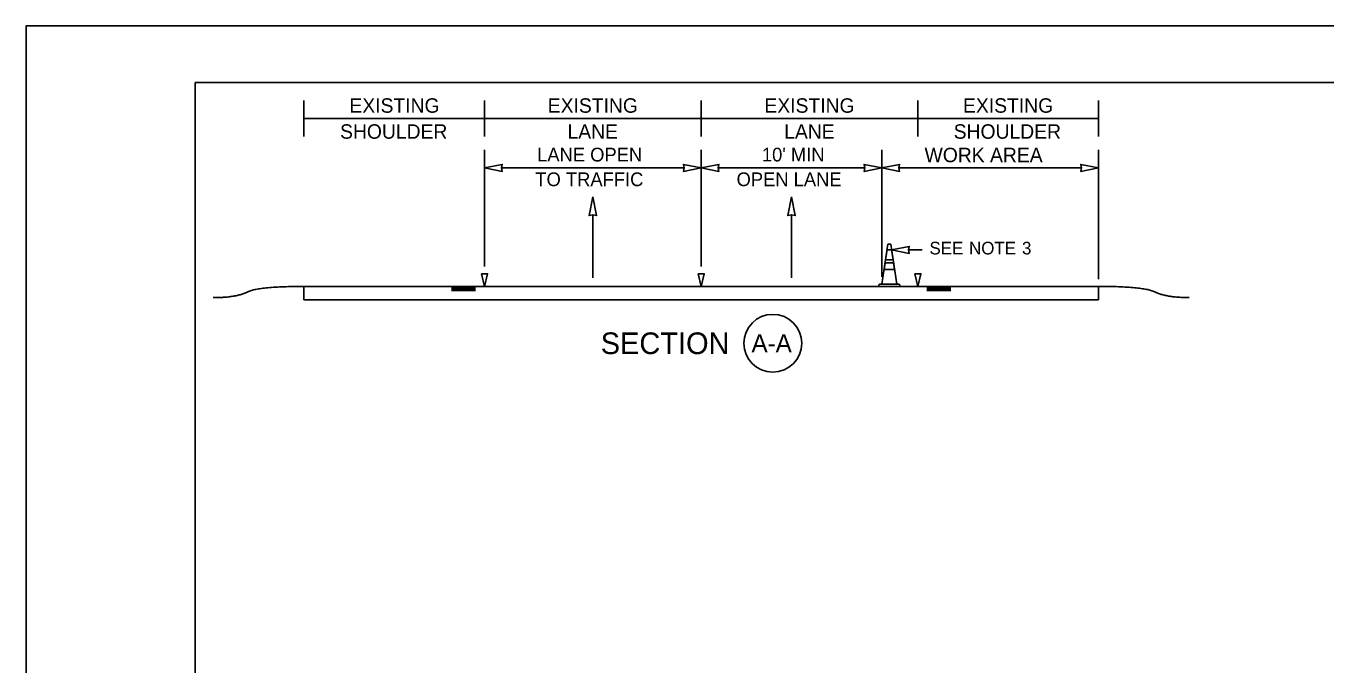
# Model space of a CAD drawing. Extents: x 99999.1 to 100055.7, y 99995 to 100010.7.
# Drawn here: x 100019.06 to 100026.26, y 100007.15 to 100010.69 of the extents above; entities that cross this region are included whole.
import ezdxf

# ---------------------------------------------------------------- set-up
doc = ezdxf.new("R2010")
doc.units = 0
for name, color, linetype in [('SH_GI_PlotLimits', 7, 'Continuous'), ('SH_GI_SheetBorder', 7, 'Continuous'), ('SH_TI_WZSectionCut', 7, 'Continuous'), ('TR_WZ_ArrowLeftStrRightTurn', 7, 'Continuous'), ('TR_WZ_TrafficConeElev', 7, 'Continuous'), ('TR_WZ_WorkZoneDetails', 7, 'Continuous'), ('TR_WZ_WorkZoneTextCurrent', 7, 'Continuous')]:
    doc.layers.add(name, color=color, linetype=linetype)

msp = doc.modelspace()

# ---------------------------------------------------------------- linework, layer by layer
at = {"layer": 'SH_GI_PlotLimits'}
msp.add_lwpolyline([(100019.0625, 99999.6875), (100036.0625, 99999.6875), (100036.0625, 100010.6875), (100019.0625, 100010.6875)], close=True, dxfattribs=at)
at = {"layer": 'SH_GI_SheetBorder'}
for q in [(100020, 100000), (100035.75, 100010.375)]:
    msp.add_line((100020, 100010.375), q, dxfattribs=at)
at = {"layer": 'SH_TI_WZSectionCut'}
for p, q in [((100020.6021, 100010.075), (100020.6021, 100010.275)), ((100021.6021, 100010.075), (100021.6021, 100010.275)), ((100022.8021, 100010.075), (100022.8021, 100010.275)), ((100024.0021, 100010.075), (100024.0021, 100010.275)), ((100025.0021, 100010.075), (100025.0021, 100010.275)), ((100020.6021, 100010.175), (100021.6021, 100010.175)), ((100021.6021, 100010.175), (100022.8021, 100010.175)), ((100022.8021, 100010.175), (100024.0021, 100010.175)), ((100024.0021, 100010.175), (100025.0021, 100010.175)), ((100021.6021, 100009.3547), (100021.6021, 100010.001)), ((100022.8021, 100009.3547), (100022.8021, 100010.001)), ((100023.8021, 100009.2975), (100023.8021, 100010.001)), ((100025.0021, 100009.2849), (100025.0021, 100010.001)), ((100021.6958, 100009.901), (100022.7084, 100009.901)), ((100021.6958, 100009.901), (100022.7084, 100009.901)), ((100022.8958, 100009.901), (100023.7084, 100009.901)), ((100023.8958, 100009.901), (100024.9084, 100009.901)), ((100020.6021, 100009.2449), (100020.6021, 100009.1699)), ((100025.0021, 100009.2449), (100020.6021, 100009.2449)), ((100021.4191, 100009.2397), (100021.5521, 100009.2397)), ((100021.4191, 100009.2341), (100021.5521, 100009.2341)), ((100021.4191, 100009.2284), (100021.5521, 100009.2284)), ((100021.4191, 100009.2232), (100021.5521, 100009.2232)), ((100024.1851, 100009.2393), (100024.0521, 100009.2393)), ((100024.1851, 100009.2337), (100024.0521, 100009.2337)), ((100024.1851, 100009.228), (100024.0521, 100009.228)), ((100024.1851, 100009.2228), (100024.0521, 100009.2228)), ((100025.0021, 100009.2449), (100025.0021, 100009.1699)), ((100025.0021, 100009.1699), (100020.6021, 100009.1699))]:
    msp.add_line(p, q, dxfattribs=at)
for points in [[(100021.6021, 100009.901), (100021.7004, 100009.8817), (100021.6958, 100009.901), (100021.7004, 100009.9203)], [(100022.8021, 100009.901), (100022.7038, 100009.8817), (100022.7084, 100009.901), (100022.7038, 100009.9203)], [(100022.8021, 100009.901), (100022.9004, 100009.8817), (100022.8958, 100009.901), (100022.9004, 100009.9203)], [(100023.8021, 100009.901), (100023.7038, 100009.8817), (100023.7084, 100009.901), (100023.7038, 100009.9203)], [(100023.8021, 100009.901), (100023.9004, 100009.8817), (100023.8958, 100009.901), (100023.9004, 100009.9203)], [(100025.0021, 100009.901), (100024.9038, 100009.8817), (100024.9084, 100009.901), (100024.9038, 100009.9203)], [(100021.5854, 100009.3147), (100021.6188, 100009.3147), (100021.6021, 100009.2449)], [(100022.7854, 100009.3147), (100022.8188, 100009.3147), (100022.8021, 100009.2449)], [(100023.9854, 100009.3147), (100024.0188, 100009.3147), (100024.0021, 100009.2449)]]:
    msp.add_lwpolyline(points, close=True, dxfattribs=at)
msp.add_circle((100023.1987, 100008.93), 0.16, dxfattribs=at)
for points in [[(100020.6021, 100009.2449), (100020.3509, 100009.2449), (100020.2255, 100009.1828), (100020.1, 100009.1828)], [(100025.0021, 100009.2449), (100025.2533, 100009.2451), (100025.3788, 100009.183), (100025.5043, 100009.1831)]]:
    msp.add_open_spline(points, degree=2, dxfattribs=at)
at = {"layer": 'TR_WZ_ArrowLeftStrRightTurn'}
for p, q in [((100022.2021, 100009.6418), (100022.2021, 100009.292)), ((100023.3021, 100009.6418), (100023.3021, 100009.292))]:
    msp.add_line(p, q, dxfattribs=at)
for points in [[(100022.2021, 100009.742), (100022.1815, 100009.6369), (100022.2021, 100009.6418), (100022.2227, 100009.6369)], [(100023.3021, 100009.742), (100023.2815, 100009.6369), (100023.3021, 100009.6418), (100023.3227, 100009.6369)]]:
    msp.add_lwpolyline(points, close=True, dxfattribs=at)
at = {"layer": 'TR_WZ_TrafficConeElev'}
for p, q in [((100023.8229, 100009.3929), (100023.8312, 100009.4471)), ((100023.8312, 100009.4471), (100023.8564, 100009.4471)), ((100023.8564, 100009.4471), (100023.8647, 100009.3929)), ((100023.8146, 100009.3388), (100023.8203, 100009.3763)), ((100023.873, 100009.3388), (100023.8146, 100009.3388)), ((100023.8203, 100009.3763), (100023.8672, 100009.3763)), ((100023.8647, 100009.3929), (100023.8229, 100009.3929)), ((100023.8672, 100009.3763), (100023.873, 100009.3388)), ((100023.786, 100009.2533), (100023.7901, 100009.2575)), ((100023.786, 100009.245), (100023.786, 100009.2533)), ((100023.9016, 100009.245), (100023.786, 100009.245)), ((100023.8854, 100009.2575), (100023.8974, 100009.2575)), ((100023.8974, 100009.2575), (100023.9016, 100009.2533)), ((100023.9016, 100009.2533), (100023.9016, 100009.245))]:
    msp.add_line(p, q, dxfattribs=at)
msp.add_lwpolyline([(100023.8854, 100009.2575), (100023.8021, 100009.2575), (100023.836, 100009.4783), (100023.8516, 100009.4783)], close=True, dxfattribs=at)
msp.add_lwpolyline([(100023.8854, 100009.2575), (100023.8021, 100009.2575), (100023.836, 100009.4783), (100023.8516, 100009.4783)], close=True, dxfattribs=at)
msp.add_lwpolyline([(100023.7901, 100009.2575), (100023.8021, 100009.2575), (100023.8854, 100009.2575)], dxfattribs=at)
at = {"layer": 'TR_WZ_WorkZoneDetails'}
msp.add_line((100024.0263, 100009.4471), (100023.9501, 100009.4471), dxfattribs=at)
msp.add_lwpolyline([(100023.8564, 100009.4471), (100023.9547, 100009.4279), (100023.9501, 100009.4472), (100023.9546, 100009.4664)], close=True, dxfattribs=at)

# ---------------------------------------------------------------- texts
at = {"layer": 'SH_TI_WZSectionCut'}
for s, height, p in [('EXISTING', 0.08, (100020.8538, 100010.207)), ('EXISTING', 0.08, (100021.9523, 100010.207)), ('EXISTING', 0.08, (100023.1523, 100010.207)), ('EXISTING', 0.08, (100024.2523, 100010.207)), ('SHOULDER', 0.08, (100020.8019, 100010.063)), ('LANE', 0.08, (100022.0617, 100010.063)), ('LANE', 0.08, (100023.2617, 100010.063)), ('SHOULDER', 0.08, (100024.2004, 100010.063)), ('SECTION', 0.12, (100022.2456, 100008.87)), ('A-A', 0.1, (100023.0808, 100008.88))]:
    msp.add_text(s, height=height, rotation=360, dxfattribs=at).set_placement(p)
for s, height, p in [('LANE OPEN', 0.076, (100021.8934, 100009.937)), ("10' MIN", 0.076, (100023.1382, 100009.937)), ('WORK AREA', 0.08, (100024.0392, 100009.933)), ('TO TRAFFIC', 0.076, (100021.8834, 100009.8002)), ('OPEN LANE', 0.076, (100022.9979, 100009.8002))]:
    msp.add_text(s, height=height, dxfattribs=at).set_placement(p)
at = {"layer": 'TR_WZ_WorkZoneTextCurrent'}
for s, p in [('SEE', (100024.0663, 100009.4221)), ('NOTE', (100024.2856, 100009.4221)), ('3', (100024.5788, 100009.4221))]:
    msp.add_text(s, height=0.07, dxfattribs=at).set_placement(p)

doc.saveas('drawing.dxf')
